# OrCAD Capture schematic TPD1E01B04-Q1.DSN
size A; title: TPD1E01B04-Q1 Automotive ESD Protection Diode; rev: 1.0; note: Datasheet: SLVSG26A
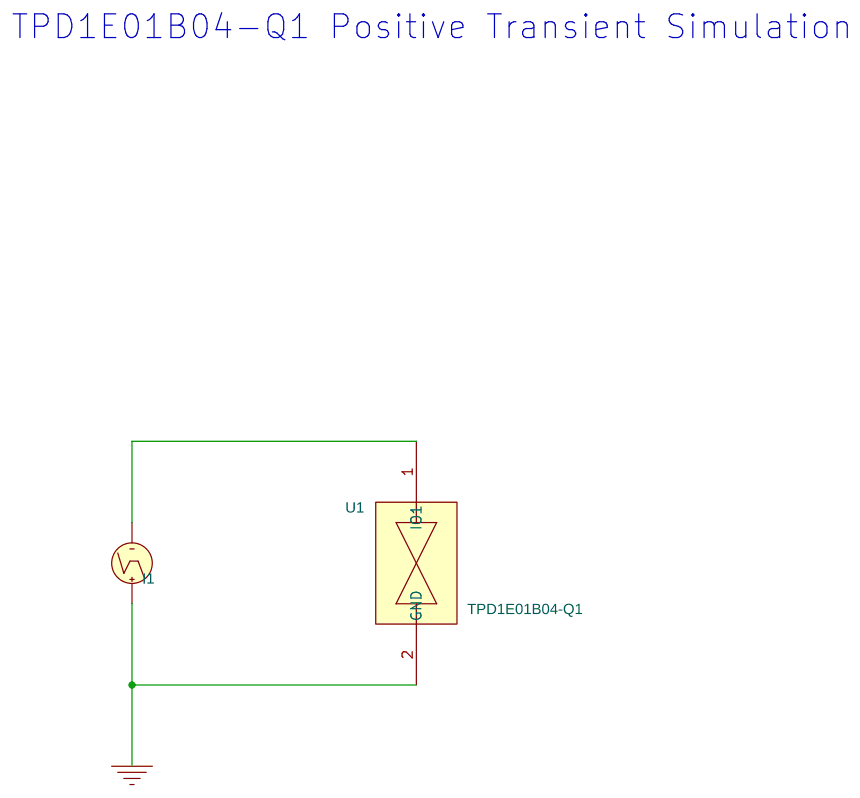
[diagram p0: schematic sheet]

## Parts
I1  IPWL_GENERIC
U1  TPD1E01B04-Q1

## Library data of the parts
I1 = IPWL_GENERIC: AppProp: No_reps$POINTS_TYPE_PWL$0$0; FIRST_NPAIRS: 0n 0 0.8n 30 6n 8 9.5n 12.5 10n 13 18n 16 22n 16 25n 16 60n 9 72n 7 82n 5.3 150n 0; PSpiceTemplate: I^@REFDES %+ %- ?DC|DC @DC| ?AC|AC @AC| PWL ?TSF|TIME_SCALE_FACTOR=@TSF| ?VSF|VALUE_SCALE_FACTOR=@VSF| ?REPEAT_VALUE| \n+ REPEAT FOR @REPEAT_VALUE| \n+ @FIRST_NPAIRS ?SECOND_NPAIRS|\n+ @SECOND_NPAIRS ?THIRD_NPAIRS/\n+ @THIRD_NPAIRS/| ?REPEAT_VALUE| \n+ ENDREPEAT|
U1 = TPD1E01B04-Q1

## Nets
0: I1.1(+) U1.2(GND)
N02772: I1.2(-) U1.1(IO1)

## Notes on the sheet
- TPD1E01B04-Q1 Positive Transient Simulation
